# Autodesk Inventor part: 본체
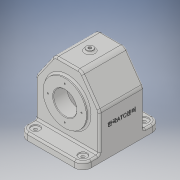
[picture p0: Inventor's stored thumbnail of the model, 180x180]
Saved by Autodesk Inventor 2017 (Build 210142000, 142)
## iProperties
Part Number: 본체
Material: 일반
Document SubType Name: Modeling
Designer: MRC
Density: 1 g/cm^3
Appearance: 기본값
Author: MRC
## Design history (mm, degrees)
sketch "스케치1"
  geometry: L1 (-55, -65)-(-55, 12); L2 (-55, 12)-(-23.491, 57); L3 (-23.491, 57)-(23.491, 57); L4 (23.491, 57)-(55, 12); L5 (55, 12)-(55, -65); L6 (55, -65)-(-55, -65); 3 further points
  constraints: 12 end point, 2 midpoint, 2 vertical, 2 vertical alignment, 1 horizontal alignment, 1 parallel, 1 perpendicular
  dimensions: "d0" = 65 distance from line of L6 point (0, 0); "d1" = 77 distance of L1.start L1.end; "d3" = 122 distance between parallel lines of L6 L3; "d4" = 110 distance between parallel lines of L5 L1; "d5" = 35 deg angle of L1 L2
extrude "돌출1" new body sketch "스케치1" stored distance "d6" = 77; taper "d7" = 0 deg
feature "쉘1" dims "d8" = 5
sketch "스케치4"
  geometry: C1 r 37.5 at (0, 0); 1 further point
  constraints: 1 centre point, 1 coincident
  dimensions: "d15" = 75 diameter of C1
extrude "돌출3" join sketch "스케치4" distance "d16" = 5; taper "d17" = 0 deg
sketch "스케치5"
  geometry: C1 r 31 at (0, 0); 1 further point
  constraints: 1 centre point, 1 coincident
  dimensions: "d18" = 62 diameter of C1
extrude "돌출4" join sketch "스케치5" distance "d19" = 10; taper "d20" = 0 deg
sketch "스케치7"
  geometry: L1 (0, 0)-(110, 0) reference; L2 (110, 0)-(110, 28.5); L3 (110, 28.5)-(0, 28.5); L4 (0, 28.5)-(0, 0); L5 (105, -72)-(5, -72) reference; L6 (5, -72)-(5, -5) reference; L7 (5, -5)-(105, -5) reference; L8 (105, -5)-(105, -72) reference; L9 (110, 0)-(110, -77) reference; L10 (0, 0)-(110, 0) reference; L11 (0, -77)-(0, 0) reference; L12 (110, -77)-(0, -77) reference; 1 further point
  constraints: 6 end point, 2 perpendicular, 1 vertical
  dimensions: "d21" = 67 distance from line of L3 point (55, -38.5)
extrude "돌출5" join sketch "스케치7" distance "d22" = 12; taper "d23" = 0 deg
node "작업 평면1"
sketch "스케치9"
  geometry: C1 r 27 at (0, 0); 1 further point
  constraints: 1 centre point, 1 coincident
  dimensions: "d25" = 54 diameter of C1
extrude "돌출6" join sketch "스케치9" stored distance "d26" = 12; taper "d27" = 45 deg
hole "구멍1" diameter "d30" = 40; stored, may be unused: countersink angle "d34" = 90 deg, drill point angle "d36" = 0 deg; dims "d28" = 10, "d29" = 10, "d31" = 6, "d32" = 4, "d33" = 2, "d35" = 50
hole "구멍2" diameter "d39" = 40; stored, may be unused: countersink angle "d43" = 90 deg, drill point angle "d45" = 0 deg; dims "d37" = 10, "d38" = 10, "d40" = 6, "d41" = 4, "d42" = 2, "d44" = 15
node "작업 평면2"
sketch "스케치11"
  geometry: C1 r 6 at (0, 0); 1 further point
  constraints: 1 centre point, 1 coincident
  dimensions: "d47" = 12 diameter of C1
extrude "돌출7" join sketch "스케치11" stored distance "d48" = 12; taper "d49" = 0 deg
sketch "스케치12"
  geometry: A1 r 29 centre (0, 0) between (0, 29) and (29, 0); 3 further points
  constraints: 4 point on circle, 2 horizontal alignment, 2 vertical alignment, 1 centre point, 1 coincident
  dimensions: "d50" = 58 diameter of A1
hole "구멍3" sketch "스케치12" at (0, 29), (29, 0), (-29, 0), (0, -29) diameter "d51" = 2.459; stored, may be unused: countersink angle "d55" = 90 deg, drill point angle "d57" = 118 deg; dims "d52" = 6, "d53" = 4, "d54" = 2, "d56" = 8
sketch "스케치13"
  geometry: A1 r 26 centre (0, 0) between (0, 26) and (26, 0); 3 further points
  constraints: 4 point on circle, 2 horizontal alignment, 2 vertical alignment, 1 centre point, 1 coincident
  dimensions: "d58" = 52 diameter of A1
hole "구멍4" sketch "스케치13" at (0, 26), (26, 0), (0, -26), (-26, 0) diameter "d59" = 2.459; stored, may be unused: countersink angle "d63" = 90 deg, drill point angle "d65" = 118 deg; dims "d60" = 6, "d61" = 4, "d62" = 2, "d64" = 8
hole "구멍5" diameter "d68" = 5.188; stored, may be unused: countersink angle "d72" = 90 deg, drill point angle "d74" = 118 deg; dims "d66" = 10, "d67" = 10, "d69" = 30, "d70" = 4, "d71" = 2, "d73" = 30
fillet "모깎기1" dims "d75" = 14
node "작업 평면3"
sketch "스케치15"
  geometry: L1 (-53, 38.5)-(12, 38.5) reference; L2 (-65, 53)-(-65, -53) reference; 7 further points; 1 other entity
  constraints: 2 other
  dimensions: "d85" = 38.5 distance from line of L1 point (-15, 0); "d95" = 50 distance from line of L2 point (-15, 0)
feature "엠보싱1" sketch "스케치15" dims "d0" = 65, "d1" = 77, "d3" = 122, "d4" = 110, "d5" = 35 deg, "d86" = 0.5, "d87" = 0
fillet "모깎기2" dims "d88" = 10
sketch "스케치17"
  geometry: A1 r 14 centre (14, -14.5) between (0, -14.5) and (14, -28.5) reference; A2 r 14 centre (96, -14.5) between (96, -28.5) and (110, -14.5) reference; A3 r 14 centre (14, 91.5) between (14, 105.5) and (0, 91.5) reference; A4 r 14 centre (96, 91.5) between (110, 91.5) and (96, 105.5) reference; 5 further points
  constraints: 4 coincident
hole "구멍7" sketch "스케치17" at (14, -14.5), (96, -14.5), (14, 91.5), (96, 91.5) diameter "d96" = 5.5; stored, may be unused: countersink angle "d100" = 90 deg, drill point angle "d102" = 118 deg; dims "d97" = 6, "d98" = 15, "d99" = 2, "d101" = 12
fillet "모깎기3" dims "d89" = 3
fillet "모깎기4" dims "d90" = 5
fillet "모깎기5" dims "d91" = 3
chamfer "모따기1" distance "d92" = 1; stored, may be unused: second distance "d93" = 2, angle "d94" = 45 deg
sketch "스케치16"
  geometry: 1 further point
node "솔리드1"
mirror "미러1"
node "투영된 루프1"
other parameters: "d24" = -24, "d46" = 61, "d83" = 115.5
